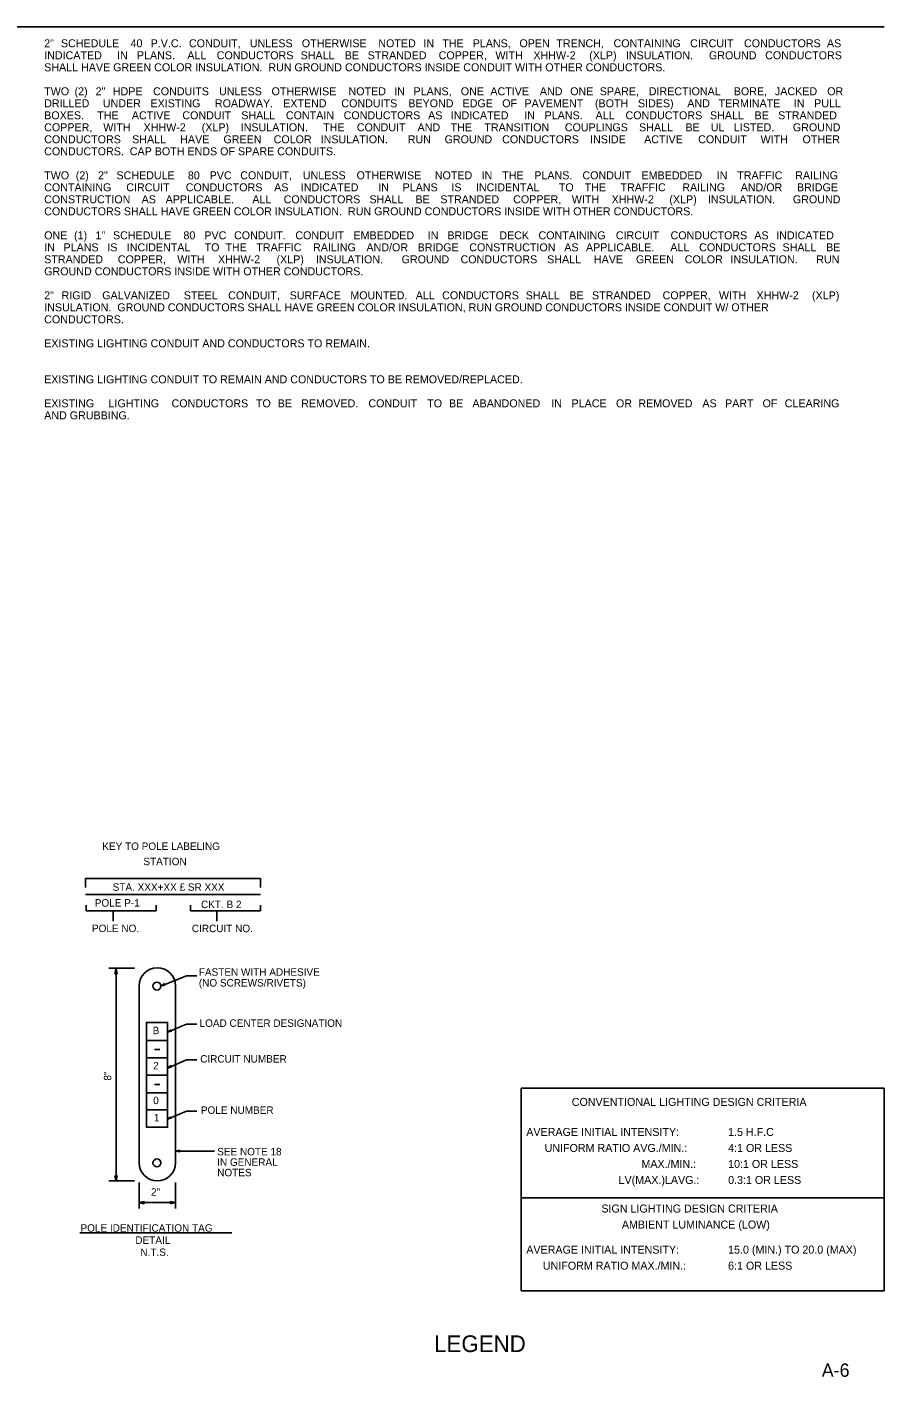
# Model space of a CAD drawing. Extents: x -1500 to -654, y -278 to 331.
# Drawn here: x -976 to -654, y -266 to 241 of the extents above; entities that cross this region are included whole.
import ezdxf

# ---------------------------------------------------------------- set-up
doc = ezdxf.new("R2010")
doc.units = 0
for name, color, linetype in [('Default', 7, 'Continuous'), ('Miscellaneous3', 7, 'Continuous'), ('NonPlottingEle_dp', 7, 'Continuous'), ('PlotBorder_dp', 7, 'Continuous'), ('SheetBorder_dp', 7, 'Continuous'), ('SheetLines_dp', 7, 'Continuous')]:
    doc.layers.add(name, color=color, linetype=linetype)

msp = doc.modelspace()

# ---------------------------------------------------------------- linework, layer by layer
at = {"layer": 'Miscellaneous3'}
msp.add_line((-1424.17, 240.54), (-654.17, 240.54), dxfattribs=at)
at = {"layer": 'PlotBorder_dp'}
for p, q in [((-953.56, -78.74), (-953.56, -82.05)), ((-953.56, -78.74), (-887.93, -78.74)), ((-887.93, -78.74), (-887.93, -82.05)), ((-953.56, -84.76), (-887.93, -84.76)), ((-953.31, -90.87), (-953.31, -88.73)), ((-953.31, -90.87), (-927.04, -90.87)), ((-943.23, -90.87), (-943.23, -94.69)), ((-927.04, -90.87), (-927.04, -88.73)), ((-914.2, -90.87), (-914.2, -88.73)), ((-914.2, -90.87), (-887.93, -90.87)), ((-904.3, -90.87), (-904.3, -94.69)), ((-887.93, -90.87), (-887.93, -88.73)), ((-944.84, -112.31), (-935.28, -112.31)), ((-942.62, -114.45), (-942.16, -112.57)), ((-941.67, -114.45), (-942.62, -114.45)), ((-942.16, -112.28), (-942.16, -192.04)), ((-942.16, -112.57), (-941.67, -114.45)), ((-915.78, -115.25), (-925.3, -119.05)), ((-911.84, -115.25), (-915.78, -115.25)), ((-933.52, -119.01), (-933.52, -185.31)), ((-924.02, -118.13), (-925.3, -119.05)), ((-924.02, -118.33), (-925.3, -119.05)), ((-924.02, -118.33), (-925.3, -119.05)), ((-925.3, -119.05), (-924.02, -118.33)), ((-925.3, -119.05), (-923.82, -118.5)), ((-925.3, -119.05), (-924.02, -118.5)), ((-924.02, -118.5), (-925.3, -119.05)), ((-925.3, -119.05), (-923.82, -118.69)), ((-923.82, -118.69), (-924.02, -118.13)), ((-924.02, -118.13), (-924.02, -118.33)), ((-923.82, -118.5), (-924.02, -118.33)), ((-924.02, -118.33), (-924.02, -118.33)), ((-924.02, -118.5), (-924.02, -118.33)), ((-924.02, -118.33), (-924.02, -118.5)), ((-924.02, -118.33), (-924.02, -118.5)), ((-919.85, -185.31), (-919.85, -119.01)), ((-930.73, -132.68), (-930.73, -172)), ((-922.84, -132.68), (-930.73, -132.68)), ((-922.84, -172), (-922.84, -132.68)), ((-915.78, -133.3), (-922.84, -136.36)), ((-921.56, -135.44), (-922.84, -136.36)), ((-921.56, -135.64), (-922.84, -136.36)), ((-921.56, -135.64), (-922.84, -136.36)), ((-922.84, -136.36), (-921.56, -135.64)), ((-922.84, -136.36), (-921.37, -135.8)), ((-922.84, -136.36), (-921.56, -135.8)), ((-921.56, -135.8), (-922.84, -136.36)), ((-922.84, -136.36), (-921.37, -136)), ((-921.37, -136), (-921.56, -135.44)), ((-921.56, -135.44), (-921.56, -135.64)), ((-921.37, -135.8), (-921.56, -135.64)), ((-921.56, -135.64), (-921.56, -135.64)), ((-921.56, -135.8), (-921.56, -135.64)), ((-921.56, -135.64), (-921.56, -135.8)), ((-921.56, -135.64), (-921.56, -135.8)), ((-911.84, -133.3), (-915.78, -133.3)), ((-922.84, -139.41), (-930.73, -139.41)), ((-922.84, -145.98), (-930.73, -145.98)), ((-915.78, -146.71), (-922.84, -149.8)), ((-911.84, -146.71), (-915.78, -146.71)), ((-921.56, -148.84), (-922.84, -149.8)), ((-921.56, -149.04), (-922.84, -149.8)), ((-921.56, -149.04), (-922.84, -149.8)), ((-922.84, -149.8), (-921.56, -149.04)), ((-922.84, -149.8), (-921.37, -149.24)), ((-922.84, -149.8), (-921.56, -149.24)), ((-921.56, -149.24), (-922.84, -149.8)), ((-922.84, -149.8), (-921.37, -149.4)), ((-921.37, -149.4), (-921.56, -148.84)), ((-921.56, -148.84), (-921.56, -149.04)), ((-921.37, -149.24), (-921.56, -149.04)), ((-921.56, -149.04), (-921.56, -149.04)), ((-921.56, -149.24), (-921.56, -149.04)), ((-921.56, -149.04), (-921.56, -149.24)), ((-921.56, -149.04), (-921.56, -149.24)), ((-922.84, -152.52), (-930.73, -152.52)), ((-922.84, -159.09), (-930.73, -159.09)), ((-922.84, -165.46), (-930.73, -165.46)), ((-915.78, -165.92), (-922.84, -168.98)), ((-911.84, -165.92), (-915.78, -165.92)), ((-922.84, -172), (-930.73, -172)), ((-930.73, -172), (-922.84, -172)), ((-921.56, -168.06), (-922.84, -168.98)), ((-921.56, -168.22), (-922.84, -168.98)), ((-921.56, -168.22), (-922.84, -168.98)), ((-922.84, -168.98), (-921.56, -168.22)), ((-922.84, -168.98), (-921.37, -168.42)), ((-922.84, -168.98), (-921.56, -168.42)), ((-921.56, -168.42), (-922.84, -168.98)), ((-922.84, -168.98), (-921.37, -168.62)), ((-921.37, -168.62), (-921.56, -168.06)), ((-921.56, -168.06), (-921.56, -168.22)), ((-921.37, -168.42), (-921.56, -168.22)), ((-921.56, -168.22), (-921.56, -168.22)), ((-921.56, -168.42), (-921.56, -168.22)), ((-921.56, -168.22), (-921.56, -168.42)), ((-921.56, -168.22), (-921.56, -168.42)), ((-942.16, -192.04), (-942.16, -178.38)), ((-918.29, -180.57), (-919.85, -180.91)), ((-918.29, -180.57), (-919.85, -180.91)), ((-918.26, -180.85), (-919.85, -180.91)), ((-919.85, -180.91), (-918.26, -180.85)), ((-918.26, -180.85), (-919.85, -180.91)), ((-919.85, -180.91), (-918.26, -180.85)), ((-910.81, -180.91), (-919.85, -180.91)), ((-919.85, -180.91), (-918.27, -181.27)), ((-919.85, -180.91), (-918.34, -181)), ((-918.34, -181), (-918.29, -180.57)), ((-918.3, -180.57), (-918.3, -180.57)), ((-918.27, -181.27), (-918.29, -180.57)), ((-918.29, -180.57), (-918.26, -180.85)), ((-918.27, -180.85), (-918.27, -180.85)), ((-918.27, -180.85), (-918.27, -180.85)), ((-918.27, -180.85), (-918.27, -180.85)), ((-910.81, -180.91), (-905.19, -180.91)), ((-944.84, -192.08), (-935.28, -192.08)), ((-942.16, -192.04), (-942.62, -190.17)), ((-942.62, -190.17), (-941.67, -190.17)), ((-941.67, -190.17), (-942.16, -192.04)), ((-926.79, -192.04), (-926.79, -192.04)), ((-933.52, -192.68), (-933.52, -202.43)), ((-919.85, -192.68), (-919.85, -202.43)), ((-933.52, -200.25), (-931.65, -199.79)), ((-919.85, -200.25), (-933.52, -200.25)), ((-933.52, -200.25), (-919.85, -200.25)), ((-931.65, -200.71), (-933.52, -200.25)), ((-931.65, -199.79), (-931.65, -200.71)), ((-921.73, -199.79), (-919.85, -200.25)), ((-921.73, -200.71), (-921.73, -199.79)), ((-919.85, -200.25), (-921.73, -200.71)), ((-955.71, -211.55), (-898.77, -211.55))]:
    msp.add_line(p, q, dxfattribs=at)
for points in [[(-930.73, -139.41), (-922.84, -139.41), (-922.84, -132.68), (-930.73, -132.68)], [(-930.73, -152.52), (-922.84, -152.52), (-922.84, -145.98), (-930.73, -145.98)], [(-930.73, -159.09), (-922.84, -159.09), (-922.84, -165.46), (-930.73, -165.46)], [(-930.73, -165.46), (-922.84, -165.46), (-922.84, -172), (-930.73, -172)]]:
    msp.add_lwpolyline(points, close=True, dxfattribs=at)
for points in [[(-927.77, -142.83), (-925.7, -142.83)], [(-927.77, -155.94), (-925.7, -155.94)]]:
    msp.add_lwpolyline(points, dxfattribs=at)
for centre in [(-926.8, -119.05), (-926.8, -185.34)]:
    msp.add_circle(centre, 1.5, dxfattribs=at)
for centre, start, end in [((-926.69, -119.01), 0, 180), ((-926.69, -185.31), 180, 0)]:
    msp.add_arc(centre, 6.83, start, end, dxfattribs=at)
at = {"layer": 'SheetLines_dp'}
for points in [[(-790.22, -157.37), (-654.17, -157.37), (-654.17, -198.41), (-790.22, -198.41)], [(-790.22, -198.41), (-654.17, -198.41), (-654.17, -233.32), (-790.22, -233.32)]]:
    msp.add_lwpolyline(points, close=True, dxfattribs=at)

# ---------------------------------------------------------------- texts
at = {"layer": 'Default'}
msp.add_text('CONVENTIONAL LIGHTING DESIGN CRITERIA', height=3, dxfattribs=at).set_placement((-771.26, -164))
at = {"layer": 'NonPlottingEle_dp'}
msp.add_text('A-6', height=5, dxfattribs=at).set_placement((-677.51, -265.57))
at = {"layer": 'PlotBorder_dp'}
for s, height, p in [('KEY TO POLE LABELING', 2.8, (-947.3, -68.03)), ('STATION', 2.8, (-931.89, -73.74)), ('STA. XXX+XX £ SR XXX', 2.8, (-943.42, -83.34)), ('POLE P-1', 2.8, (-950.12, -89.27)), ('CKT. B 2', 2.8, (-910.29, -89.84)), ('POLE NO.', 2.8, (-951.17, -98.82)), ('CIRCUIT NO.', 2.8, (-913.72, -98.85)), ('(NO SCREWS/RIVETS)', 2.8, (-911.1, -119.24)), ('FASTEN WITH ADHESIVE', 2.8, (-911.1, -115.19)), ('LOAD CENTER DESIGNATION', 2.8, (-910.82, -134.35)), ('B', 2.8, (-928.4, -137.1)), ('CIRCUIT NUMBER', 2.8, (-910.59, -147.76)), ('2', 2.8, (-928.25, -150.3)), ('0', 2.8, (-928.21, -163.33)), ('1', 2.8, (-927.94, -169.78)), ('POLE NUMBER', 2.8, (-910.33, -166.97)), ('AVERAGE INITIAL INTENSITY:', 3, (-788.31, -175.26)), ('1.5 H.F.C', 3, (-712.63, -175.26)), ('SEE NOTE 18', 2.8, (-904.21, -182.54)), ('UNIFORM RATIO AVG./MIN.:', 3, (-781.44, -181.26)), ('4:1 OR LESS', 3, (-712.63, -181.26)), ('IN GENERAL ', 2.8, (-904.21, -186.46)), ('MAX./MIN.:', 3, (-745.13, -187.26)), ('10:1 OR LESS', 3, (-712.63, -187.26)), ('NOTES', 2.8, (-904.21, -190.38)), ('LV(MAX.)LAVG.:', 3, (-753.7, -193.26)), ('0.3:1 OR LESS', 3, (-712.63, -193.26)), ('2"', 2.8, (-929.04, -197.67)), ('SIGN LIGHTING DESIGN CRITERIA', 3, (-760.16, -203.98)), ('AMBIENT LUMINANCE (LOW)', 3, (-752.47, -209.98)), ('POLE IDENTIFICATION TAG ', 2.8, (-955.47, -211.16)), ('DETAIL', 2.8, (-934.9, -215.71)), ('N.T.S.', 2.8, (-933.01, -220.26)), ('AVERAGE INITIAL INTENSITY:', 3, (-788.31, -219.39)), ('15.0 (MIN.) TO 20.0 (MAX)', 3, (-712.63, -219.39)), ('UNIFORM RATIO MAX./MIN.:', 3, (-782.09, -225.39)), ('6:1 OR LESS', 3, (-712.63, -225.39)), ('            LEGEND             ', 6.25, (-850.74, -256.28))]:
    msp.add_text(s, height=height, dxfattribs=at).set_placement(p)
msp.add_text('8"', height=2.8, rotation=90, dxfattribs=at).set_placement((-943.91, -154.51))
at = {"layer": 'SheetBorder_dp'}
for s, p in [('2" ', (-969.09, 232.93)), ('SCHEDULE ', (-962.82, 232.93)), ('40 ', (-936.71, 232.93)), ('P.V.C. ', (-929.17, 232.93)), ('CONDUIT, ', (-914.8, 232.93)), ('UNLESS ', (-891.98, 232.93)), ('OTHERWISE ', (-872.49, 232.93)), ('NOTED ', (-843.8, 232.93)), ('IN ', (-826.87, 232.93)), ('THE ', (-819.81, 232.93)), ('PLANS, ', (-808.41, 232.93)), ('OPEN ', (-790.88, 232.93)), ('TRENCH, ', (-777.03, 232.93)), ('CONTAINING ', (-755.59, 232.93)), ('CIRCUIT ', (-726.87, 232.93)), ('CONDUCTORS ', (-706.66, 232.93)), ('AS ', (-675.58, 232.93)), ('INDICATED ', (-969.09, 228.43)), ('IN ', (-941.76, 228.43)), ('PLANS. ', (-934.32, 228.43)), (' ALL ', (-916.53, 228.43)), ('CONDUCTORS ', (-904.39, 228.43)), ('SHALL ', (-872.92, 228.43)), ('BE ', (-856.4, 228.43)), ('STRANDED ', (-847.78, 228.43)), ('COPPER, ', (-821.16, 228.43)), ('WITH ', (-799.89, 228.43)), ('XHHW-2 ', (-785.65, 228.43)), ('(XLP) ', (-764.7, 228.43)), ('INSULATION. ', (-750.97, 228.43)), (' GROUND ', (-720.93, 228.43)), ('CONDUCTORS ', (-698.73, 228.43)), ('SHALL HAVE GREEN COLOR INSULATION.  RUN GROUND CONDUCTORS INSIDE CONDUIT WITH OTHER CONDUCTORS. ', (-969.09, 223.93)), ('TWO ', (-969.09, 214.93)), ('(2) ', (-957.71, 214.93)), ('2" ', (-949.81, 214.93)), ('HDPE ', (-943.35, 214.93)), ('CONDUITS ', (-928.26, 214.93)), ('UNLESS ', (-903.53, 214.93)), ('OTHERWISE ', (-883.84, 214.93)), ('NOTED ', (-854.97, 214.93)), ('IN ', (-837.84, 214.93)), ('PLANS, ', (-830.59, 214.93)), ('ONE ', (-812.87, 214.93)), ('ACTIVE ', (-801.77, 214.93)), ('AND ', (-783.22, 214.93)), ('ONE ', (-771.86, 214.93)), ('SPARE, ', (-760.77, 214.93)), ('DIRECTIONAL ', (-742.39, 214.93)), ('BORE, ', (-710.5, 214.93)), ('JACKED ', (-695.08, 214.93)), ('OR ', (-675.47, 214.93)), ('DRILLED ', (-969.09, 210.43)), ('UNDER ', (-947.09, 210.43)), ('EXISTING ', (-929.23, 210.43)), ('ROADWAY. ', (-905.08, 210.43)), (' EXTEND ', (-880.59, 210.43)), ('CONDUITS ', (-857.65, 210.43)), ('BEYOND ', (-832.55, 210.43)), ('EDGE ', (-812.21, 210.43)), ('OF ', (-797.34, 210.43)), ('PAVEMENT ', (-789.01, 210.43)), ('(BOTH ', (-762.55, 210.43)), ('SIDES) ', (-746.45, 210.43)), ('AND ', (-727.94, 210.43)), ('TERMINATE ', (-716.21, 210.43)), ('IN ', (-687.99, 210.43)), ('PULL ', (-680.37, 210.43)), ('BOXES. ', (-969.09, 205.93)), (' THE ', (-950.31, 205.93)), ('ACTIVE ', (-936.22, 205.93)), ('CONDUIT ', (-917.27, 205.93)), ('SHALL ', (-895.18, 205.93)), ('CONTAIN ', (-878.45, 205.93)), ('CONDUCTORS ', (-856.8, 205.93)), ('AS ', (-825.13, 205.93)), ('INDICATED ', (-816.61, 205.93)), ('IN ', (-789.09, 205.93)), ('PLANS. ', (-781.44, 205.93)), (' ALL ', (-763.45, 205.93)), ('CONDUCTORS ', (-751.1, 205.93)), ('SHALL ', (-719.43, 205.93)), ('BE ', (-702.7, 205.93)), ('STRANDED ', (-693.88, 205.93)), ('COPPER, ', (-969.09, 201.43)), ('WITH ', (-946.95, 201.43)), ('XHHW-2 ', (-931.83, 201.43)), ('(XLP) ', (-910.01, 201.43)), ('INSULATION. ', (-895.41, 201.43)), ('THE ', (-864.5, 201.43)), ('CONDUIT ', (-851.85, 201.43)), ('AND ', (-829.09, 201.43)), ('THE ', (-816.67, 201.43)), ('TRANSITION ', (-804.02, 201.43)), ('COUPLINGS ', (-773.86, 201.43)), ('SHALL ', (-746.03, 201.43)), ('BE ', (-728.63, 201.43)), ('UL ', (-719.14, 201.43)), ('LISTED. ', (-710.48, 201.43)), (' GROUND ', (-689.46, 201.43)), ('CONDUCTORS ', (-969.09, 196.93)), ('SHALL ', (-936.12, 196.93)), ('HAVE ', (-918.09, 196.93)), ('GREEN ', (-901.86, 196.93)), ('COLOR ', (-883.05, 196.93)), ('INSULATION. ', (-865.42, 196.93)), (' RUN ', (-833.88, 196.93)), ('GROUND ', (-818.95, 196.93)), ('CONDUCTORS ', (-797.35, 196.93)), ('INSIDE ', (-764.38, 196.93)), ('ACTIVE ', (-744.11, 196.93)), ('CONDUIT ', (-723.85, 196.93)), ('WITH ', (-700.46, 196.93)), ('OTHER ', (-684.72, 196.93)), ('CONDUCTORS.  CAP BOTH ENDS OF SPARE CONDUITS.', (-969.09, 192.43)), ('TWO ', (-969.09, 183.43)), ('(2) ', (-957.25, 183.43)), ('2" ', (-948.89, 183.43)), ('SCHEDULE ', (-941.98, 183.43)), ('80 ', (-915.22, 183.43)), ('PVC ', (-907.04, 183.43)), ('CONDUIT, ', (-895.57, 183.43)), ('UNLESS ', (-872.1, 183.43)), ('OTHERWISE ', (-851.96, 183.43)), ('NOTED ', (-822.63, 183.43)), ('IN ', (-805.05, 183.43)), ('THE ', (-797.34, 183.43)), ('PLANS. ', (-785.3, 183.43)), ('CONDUIT ', (-767.25, 183.43)), ('EMBEDDED ', (-745.1, 183.43)), ('IN ', (-716.91, 183.43)), ('TRAFFIC ', (-709.2, 183.43)), ('RAILING ', (-687.47, 183.43)), ('CONTAINING ', (-969.09, 178.93)), ('CONSTRUCTION ', (-969.09, 174.43)), ('CIRCUIT ', (-938.3, 178.93)), ('AS ', (-932.56, 174.43)), ('APPLICABLE. ', (-923.54, 174.43)), ('CONDUCTORS ', (-916.01, 178.93)), (' ALL ', (-892.14, 174.43)), ('AS ', (-882.85, 178.93)), ('CONDUCTORS ', (-879.29, 174.43)), ('INDICATED ', (-872.85, 178.93)), ('SHALL ', (-847.12, 174.43)), ('IN ', (-843.83, 178.93)), ('PLANS ', (-834.69, 178.93)), ('BE ', (-829.88, 174.43)), ('STRANDED ', (-820.55, 174.43)), ('IS ', (-816.4, 178.93)), ('INCIDENTAL ', (-807.2, 178.93)), ('COPPER, ', (-793.23, 174.43)), ('TO ', (-776.12, 178.93)), ('WITH ', (-771.25, 174.43)), ('THE ', (-766.44, 178.93)), ('XHHW-2 ', (-756.3, 174.43)), ('TRAFFIC ', (-752.97, 178.93)), ('(XLP) ', (-734.65, 174.43)), ('RAILING ', (-729.81, 178.93)), ('INSULATION. ', (-720.21, 174.43)), ('AND/OR ', (-707.91, 178.93)), (' GROUND ', (-689.46, 174.43)), ('BRIDGE ', (-686.81, 178.93)), ('CONDUCTORS SHALL HAVE GREEN COLOR INSULATION.  RUN GROUND CONDUCTORS INSIDE WITH OTHER CONDUCTORS.  ', (-969.09, 169.93)), ('ONE ', (-969.09, 160.93)), ('(1) ', (-957.88, 160.93)), ('1" ', (-949.86, 160.93)), ('SCHEDULE ', (-943.29, 160.93)), ('80 ', (-916.87, 160.93)), ('PVC ', (-909.03, 160.93)), ('CONDUIT. ', (-897.9, 160.93)), ('CONDUIT ', (-874.91, 160.93)), ('EMBEDDED ', (-853.11, 160.93)), ('IN ', (-825.26, 160.93)), ('BRIDGE ', (-817.89, 160.93)), ('DECK ', (-798.42, 160.93)), ('CONTAINING ', (-783.74, 160.93)), ('CIRCUIT ', (-754.72, 160.93)), ('CONDUCTORS ', (-734.21, 160.93)), ('AS ', (-702.82, 160.93)), ('INDICATED ', (-694.59, 160.93)), ('IN ', (-969.09, 156.43)), ('PLANS ', (-961.84, 156.43)), ('IS ', (-945.43, 156.43)), ('INCIDENTAL ', (-938.11, 156.43)), ('TO ', (-908.93, 156.43)), ('THE ', (-901.13, 156.43)), ('TRAFFIC ', (-889.54, 156.43)), ('RAILING ', (-868.27, 156.43)), ('AND/OR ', (-848.25, 156.43)), ('BRIDGE ', (-829.04, 156.43)), ('CONSTRUCTION ', (-809.68, 156.43)), ('AS ', (-774.06, 156.43)), ('APPLICABLE. ', (-765.94, 156.43)), (' ALL ', (-735.43, 156.43)), ('CONDUCTORS ', (-723.49, 156.43)), ('SHALL ', (-692.22, 156.43)), ('BE ', (-675.88, 156.43)), ('STRANDED ', (-969.09, 151.93)), ('COPPER, ', (-941.47, 151.93)), ('WITH ', (-919.18, 151.93)), ('XHHW-2 ', (-903.93, 151.93)), ('(XLP) ', (-881.97, 151.93)), ('INSULATION. ', (-867.22, 151.93)), (' GROUND ', (-836.17, 151.93)), ('CONDUCTORS ', (-812.96, 151.93)), ('SHALL ', (-780.48, 151.93)), ('HAVE ', (-762.94, 151.93)), ('GREEN ', (-747.2, 151.93)), ('COLOR ', (-728.88, 151.93)), ('INSULATION. ', (-711.74, 151.93)), (' RUN ', (-680.69, 151.93)), ('GROUND CONDUCTORS INSIDE WITH OTHER CONDUCTORS.  ', (-969.09, 147.43)), ('2" ', (-969.09, 138.43)), ('INSULATION.  GROUND CONDUCTORS SHALL HAVE GREEN COLOR INSULATION, RUN GROUND CONDUCTORS INSIDE CONDUIT W/ OTHER ', (-969.09, 133.93)), ('RIGID ', (-962.58, 138.43)), ('GALVANIZED ', (-947.32, 138.43)), ('STEEL ', (-916.74, 138.43)), ('CONDUIT, ', (-900.09, 138.43)), ('SURFACE ', (-877.04, 138.43)), ('MOUNTED. ', (-854.3, 138.43)), ('ALL ', (-829.75, 138.43)), ('CONDUCTORS ', (-819.86, 138.43)), ('SHALL ', (-788.53, 138.43)), ('BE ', (-772.15, 138.43)), ('STRANDED ', (-763.67, 138.43)), ('COPPER, ', (-737.2, 138.43)), ('WITH ', (-716.07, 138.43)), ('XHHW-2 ', (-701.97, 138.43)), ('(XLP) ', (-681.17, 138.43)), ('CONDUCTORS.', (-969.09, 129.43)), ('EXISTING LIGHTING CONDUIT AND CONDUCTORS TO REMAIN.', (-969.09, 120.43)), ('EXISTING LIGHTING CONDUIT TO REMAIN AND CONDUCTORS TO BE REMOVED/REPLACED. ', (-969.09, 106.93)), ('AND GRUBBING.', (-969.09, 93.43)), ('EXISTING ', (-969.09, 97.93)), ('LIGHTING ', (-944.95, 97.93)), ('CONDUCTORS ', (-921.33, 97.93)), ('TO ', (-889.69, 97.93)), ('BE ', (-881.52, 97.93)), ('REMOVED. ', (-872.73, 97.93)), ('CONDUIT ', (-847.52, 97.93)), ('TO ', (-825.46, 97.93)), ('BE ', (-817.29, 97.93)), ('ABANDONED ', (-808.5, 97.93)), ('IN ', (-778.94, 97.93)), ('PLACE ', (-771.32, 97.93)), ('OR ', (-754.68, 97.93)), ('REMOVED ', (-746.3, 97.93)), ('AS ', (-722.27, 97.93)), ('PART ', (-713.78, 97.93)), ('OF ', (-699.71, 97.93)), ('CLEARING ', (-691.4, 97.93))]:
    msp.add_text(s, height=3, dxfattribs=at).set_placement(p)

doc.saveas('drawing.dxf')
